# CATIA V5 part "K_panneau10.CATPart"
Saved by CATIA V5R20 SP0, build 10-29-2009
Part number: panneau 10
Publications: "demi largeur balancier", "epaisseur pieces", "rayon congé", "Plan.00", "liaison 10/21", "liaison 3/10", "liaison 10/23 sur 10", "liaison 10/17 sur 10"
Bounding box of the stored display mesh (mm): x -60 to 30, y -1014.999 to -685.002, z -34.998 to 479.998
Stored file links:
  G:\Khaled_CFAO_2011\SIL\SIL_GR2\mdardier\Khaled\CAD_ThinkMOTION\K_panneau10.CATPart
  G:\Khaled_CFAO_2011\SIL\SIL_GR2\mdardier\Khaled\CAD_ThinkMOTION\K_ass_tandem.CATProduct
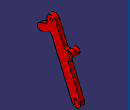
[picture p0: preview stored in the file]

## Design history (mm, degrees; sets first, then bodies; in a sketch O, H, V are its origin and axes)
External parameters (linked from other documents)
  `External.demi largeur balancier` = 50 mm
  `External.epaisseur pieces` = 30 mm
  `External.rayon congé` = 20 mm
Set1
  Plane1 "Plan.00": linked copy from another document
  Point1 "liaison 10/21": linked copy from another document
  Point2 "liaison 3/10": linked copy from another document
  Point3 "liaison 10/23 sur 10": linked copy from another document
  Point4 "liaison 10/17 sur 10": linked copy from another document
Body1 (main body)
  Sketch1 on Plane1, origin (0, 0, 0), H (0, 1, 0), V (0, 0, 1)
    construction line L1 (-910, 445) -> (-720, 0)
    point P1 (-910, 445)
    point P2 (-720, 0)
    line L2 (-877.8112, 458.7435) -> (-809.0311, 297.6533)
    line L3 (-752.1888, -13.7435) -> (-914.011, 365.2613)
    arc A1 centre (-720, 0) radius 35 from (-687.8112, 13.7435) to (-752.1888, -13.7435) cw
    arc A2 centre (-910, 445) radius 35 from (-942.1888, 431.2565) to (-877.8112, 458.7435) cw
    reference projected point E1 (-910, 445) from Point1
    reference projected point E2 (-720, 0) from Point2
    circle A3 centre (-910, 445) radius 12.5
    point P7 (-910, 445)
    reference projected point E3 (-910, 445) from Point1
    circle A4 centre (-720, 0) radius 20
    point P8 (-720, 0)
    reference projected point E4 (-720, 0) from Point2
    arc A5 centre (-990, 360) radius 25 from (-999.8168, 382.992) to (-980.1832, 337.008) ccw
    point P9 (-990, 360)
    reference projected point E5 (-990, 360) from Point3
    arc A6 centre (-775, 285) radius 25 from (-765.1832, 262.008) to (-784.8168, 307.992) ccw
    point P10 (-775, 285)
    reference projected point E6 (-775, 285) from Point4
    circle A7 centre (-775, 285) radius 12.5
    point P11 (-775, 285)
    reference projected point E7 (-775, 285) from Point4
    line L4 (-999.8168, 382.992) -> (-933.6446, 411.2453)
    point P13 (-933.6446, 411.2453)
    line L5 (-980.1832, 337.008) -> (-914.011, 365.2613)
    line L6 (-784.8168, 307.992) -> (-809.0311, 297.6533)
    line L7 (-765.1832, 262.008) -> (-789.3975, 251.6693)
    point P19 (-789.3975, 251.6693)
    line L8 (-933.6446, 411.2453) -> (-942.1888, 431.2565)
    line L9 (-789.3975, 251.6693) -> (-687.8112, 13.7435)
    distance L1 L2 = 35 {= `External.demi largeur balancier` -0.015}
    radius A3 = 12.5 {= `External.demi largeur balancier` /4}
    radius A4 = 20 {= `External.demi largeur balancier` *2/5}
    radius A5 = 25 {= `External.demi largeur balancier` /2}
    radius A6 = 25 {= `External.demi largeur balancier` /2}
    radius A7 = 12.5 {= `External.demi largeur balancier` /4}
    tangency: A1 L2, A2 L2, A1 L3, A2 L3, L5 A5, L6 A6, L4 A5, L7 A6
    coincidence: P1 E1, P2 E2, P7 E3, P8 E4, P9 E5, P10 E6, P11 E7, P13 L3, P19 L2, L3 L8, L2 L9
    perpendicularity: L4 L3, L5 L3, L6 L2, L7 L2
  Pad1: profile Sketch1, direction (1, 0, 0), length 30 {= `External.epaisseur pieces`}
  Fillet1: radius 20 {= `External.rayon congé`}, on edge [face of Pad1 from Sketch1.L4 | face of Pad1 from Sketch1.L8]; edge [face of Pad1 from Sketch1.L3 | face of Pad1 from Sketch1.L5]; edge [face of Pad1 from Sketch1.L7 | face of Pad1 from Sketch1.L9]; edge [face of Pad1 from Sketch1.L2 | face of Pad1 from Sketch1.L6]
  Sketch2 on start face of Pad1, origin (0, 0, 0), H (0, -1, 0), V (0, 0, 1)
    circle A1 centre (775, 285) radius 12.5
    point P1 (775, 285)
    reference projected point E1 (775, 285) from Point4
    circle A2 centre (775, 285) radius 25
    point P2 (775, 285)
    reference projected point E2 (775, 285) from Point4
    radius A1 = 12.5 {= `External.demi largeur balancier` /4}
    radius A2 = 25 {= `External.demi largeur balancier` /2}
    coincidence: P1 E1, P2 E2
  Pad2: profile Sketch2, direction (-1, 0, 0), length 30 {= `External.epaisseur pieces`}
  Sketch3 on start face of Pad1, origin (0, 0, 0), H (0, -1, 0), V (0, 0, 1)
    circle A1 centre (990, 360) radius 12.5
    point P1 (990, 360)
    reference projected point E1 (990, 360) from Point3
    radius A1 = 12.5 {= `External.demi largeur balancier` /4}
    coincidence: P1 E1
  Pad3: profile Sketch3, direction (-1, 0, 0), length 60 {= `External.epaisseur pieces` *2}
